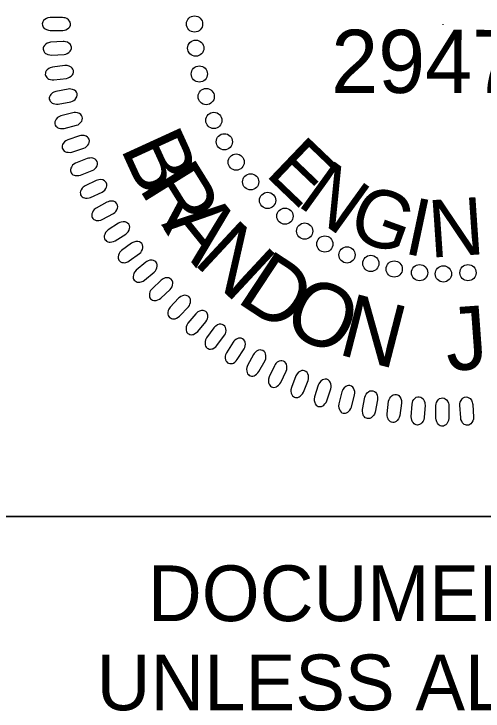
# Model space of a CAD drawing. Extents: x 505692 to 527456, y 415959 to 439886.
# Drawn here: x 507166.5 to 507212.8, y 439679.4 to 439748.2 of the extents above; entities that cross this region are included whole.
import ezdxf

# ---------------------------------------------------------------- set-up
doc = ezdxf.new("R2010")
doc.units = 0
for name, color, linetype in [('Sheet PE Seal Cell', 7, 'Continuous'), ('Sheet Profile CELL', 7, 'Continuous'), ('Sheet Sticker Exception Certification CELL', 7, 'Continuous')]:
    doc.layers.add(name, color=color, linetype=linetype)

msp = doc.modelspace()

# ---------------------------------------------------------------- linework, layer by layer
at = {"layer": 'Sheet PE Seal Cell'}
msp.add_line((507208.804, 439747.184), (507208.804, 439747.137), dxfattribs=at)
for points in [[(507171.257, 439747.846), (507170.03, 439747.847), (507169.811, 439747.809), (507169.671, 439747.758), (507169.501, 439747.645), (507169.391, 439747.548), (507169.312, 439747.435), (507169.272, 439747.331), (507169.252, 439747.219), (507169.272, 439747.107), (507169.302, 439746.987), (507169.361, 439746.883), (507169.461, 439746.778), (507169.541, 439746.718), (507169.691, 439746.651), (507169.87, 439746.591), (507170.029, 439746.569), (507171.287, 439746.561), (507171.455, 439746.583), (507171.596, 439746.628), (507171.755, 439746.718), (507171.894, 439746.83), (507171.975, 439746.927), (507172.034, 439747.084), (507172.054, 439747.233), (507172.014, 439747.383), (507171.964, 439747.487), (507171.865, 439747.615), (507171.695, 439747.734), (507171.516, 439747.801), (507171.386, 439747.831)], [(507171.309, 439745.489), (507170.085, 439745.412), (507169.868, 439745.361), (507169.732, 439745.301), (507169.569, 439745.178), (507169.466, 439745.074), (507169.393, 439744.957), (507169.36, 439744.85), (507169.348, 439744.737), (507169.375, 439744.627), (507169.412, 439744.509), (507169.478, 439744.408), (507169.584, 439744.31), (507169.667, 439744.255), (507169.821, 439744.198), (507170.004, 439744.149), (507170.164, 439744.136), (507171.419, 439744.208), (507171.587, 439744.241), (507171.723, 439744.294), (507171.877, 439744.394), (507172.009, 439744.514), (507172.083, 439744.616), (507172.133, 439744.776), (507172.143, 439744.927), (507172.094, 439745.074), (507172.038, 439745.175), (507171.931, 439745.296), (507171.754, 439745.404), (507171.57, 439745.46), (507171.439, 439745.482)], [(507171.474, 439743.108), (507170.257, 439742.955), (507170.044, 439742.89), (507169.911, 439742.821), (507169.757, 439742.688), (507169.66, 439742.578), (507169.595, 439742.457), (507169.569, 439742.348), (507169.563, 439742.234), (507169.597, 439742.126), (507169.642, 439742.011), (507169.714, 439741.914), (507169.827, 439741.823), (507169.913, 439741.773), (507170.069, 439741.725), (507170.255, 439741.688), (507170.416, 439741.686), (507171.664, 439741.836), (507171.829, 439741.879), (507171.962, 439741.941), (507172.11, 439742.05), (507172.234, 439742.178), (507172.301, 439742.285), (507172.341, 439742.448), (507172.342, 439742.599), (507172.284, 439742.743), (507172.221, 439742.84), (507172.106, 439742.954), (507171.923, 439743.051), (507171.736, 439743.095), (507171.604, 439743.109)], [(507171.807, 439740.782), (507170.602, 439740.553), (507170.393, 439740.475), (507170.266, 439740.398), (507170.12, 439740.255), (507170.031, 439740.14), (507169.974, 439740.015), (507169.954, 439739.905), (507169.955, 439739.791), (507169.996, 439739.684), (507170.048, 439739.573), (507170.126, 439739.481), (507170.244, 439739.397), (507170.333, 439739.353), (507170.493, 439739.314), (507170.68, 439739.289), (507170.841, 439739.297), (507172.077, 439739.525), (507172.239, 439739.579), (507172.368, 439739.649), (507172.508, 439739.767), (507172.624, 439739.903), (507172.684, 439740.014), (507172.714, 439740.179), (507172.705, 439740.33), (507172.638, 439740.469), (507172.57, 439740.563), (507172.448, 439740.668), (507172.259, 439740.754), (507172.07, 439740.787), (507171.937, 439740.791)], [(507172.287, 439738.441), (507171.098, 439738.137), (507170.895, 439738.046), (507170.773, 439737.961), (507170.636, 439737.81), (507170.554, 439737.688), (507170.505, 439737.56), (507170.492, 439737.449), (507170.501, 439737.335), (507170.548, 439737.232), (507170.607, 439737.123), (507170.69, 439737.037), (507170.813, 439736.96), (507170.906, 439736.921), (507171.067, 439736.894), (507171.256, 439736.881), (507171.416, 439736.898), (507172.635, 439737.203), (507172.794, 439737.267), (507172.917, 439737.345), (507173.05, 439737.472), (507173.157, 439737.615), (507173.21, 439737.728), (507173.23, 439737.896), (507173.212, 439738.046), (507173.136, 439738.18), (507173.061, 439738.269), (507172.934, 439738.368), (507172.74, 439738.441), (507172.549, 439738.463), (507172.416, 439738.459)], [(507172.941, 439736.157), (507171.774, 439735.778), (507171.577, 439735.675), (507171.46, 439735.583), (507171.333, 439735.423), (507171.259, 439735.297), (507171.218, 439735.166), (507171.212, 439735.054), (507171.228, 439734.941), (507171.281, 439734.841), (507171.347, 439734.736), (507171.436, 439734.655), (507171.563, 439734.587), (507171.657, 439734.554), (507171.82, 439734.536), (507172.01, 439734.535), (507172.168, 439734.563), (507173.366, 439734.944), (507173.52, 439735.018), (507173.639, 439735.103), (507173.763, 439735.238), (507173.861, 439735.387), (507173.907, 439735.505), (507173.915, 439735.672), (507173.888, 439735.821), (507173.804, 439735.951), (507173.725, 439736.035), (507173.591, 439736.125), (507173.393, 439736.186), (507173.201, 439736.195), (507173.068, 439736.183)], [(507173.699, 439733.92), (507172.558, 439733.469), (507172.368, 439733.353), (507172.257, 439733.254), (507172.141, 439733.087), (507172.075, 439732.956), (507172.042, 439732.822), (507172.043, 439732.711), (507172.066, 439732.599), (507172.125, 439732.503), (507172.197, 439732.402), (507172.291, 439732.327), (507172.423, 439732.266), (507172.519, 439732.24), (507172.683, 439732.232), (507172.872, 439732.243), (507173.028, 439732.28), (507174.2, 439732.735), (507174.349, 439732.819), (507174.462, 439732.912), (507174.578, 439733.054), (507174.666, 439733.21), (507174.705, 439733.329), (507174.703, 439733.497), (507174.666, 439733.644), (507174.574, 439733.768), (507174.489, 439733.847), (507174.35, 439733.929), (507174.148, 439733.977), (507173.956, 439733.974), (507173.825, 439733.953)], [(507174.599, 439731.761), (507173.488, 439731.239), (507173.306, 439731.111), (507173.202, 439731.005), (507173.096, 439730.831), (507173.038, 439730.696), (507173.014, 439730.561), (507173.022, 439730.449), (507173.052, 439730.339), (507173.118, 439730.247), (507173.196, 439730.151), (507173.294, 439730.082), (507173.429, 439730.03), (507173.527, 439730.009), (507173.691, 439730.012), (507173.879, 439730.035), (507174.032, 439730.082), (507175.173, 439730.61), (507175.317, 439730.703), (507175.424, 439730.802), (507175.53, 439730.951), (507175.61, 439731.112), (507175.64, 439731.234), (507175.627, 439731.402), (507175.582, 439731.546), (507175.482, 439731.664), (507175.392, 439731.737), (507175.248, 439731.81), (507175.044, 439731.845), (507174.852, 439731.831), (507174.723, 439731.802)], [(507175.646, 439729.612), (507174.571, 439729.021), (507174.397, 439728.883), (507174.299, 439728.77), (507174.205, 439728.59), (507174.155, 439728.452), (507174.14, 439728.315), (507174.155, 439728.204), (507174.192, 439728.096), (507174.263, 439728.008), (507174.347, 439727.918), (507174.449, 439727.855), (507174.588, 439727.811), (507174.686, 439727.797), (507174.85, 439727.81), (507175.036, 439727.844), (507175.187, 439727.901), (507176.292, 439728.499), (507176.429, 439728.601), (507176.53, 439728.708), (507176.626, 439728.863), (507176.695, 439729.028), (507176.718, 439729.152), (507176.695, 439729.318), (507176.64, 439729.459), (507176.533, 439729.571), (507176.439, 439729.639), (507176.291, 439729.702), (507176.085, 439729.725), (507175.894, 439729.698), (507175.767, 439729.661)], [(507176.803, 439727.537), (507175.766, 439726.88), (507175.601, 439726.731), (507175.511, 439726.613), (507175.428, 439726.427), (507175.387, 439726.286), (507175.38, 439726.148), (507175.403, 439726.039), (507175.446, 439725.933), (507175.523, 439725.85), (507175.612, 439725.765), (507175.719, 439725.708), (507175.859, 439725.673), (507175.958, 439725.666), (507176.121, 439725.689), (507176.304, 439725.735), (507176.451, 439725.801), (507177.516, 439726.467), (507177.647, 439726.577), (507177.741, 439726.691), (507177.828, 439726.851), (507177.886, 439727.021), (507177.901, 439727.146), (507177.867, 439727.31), (507177.804, 439727.447), (507177.691, 439727.552), (507177.593, 439727.613), (507177.44, 439727.668), (507177.233, 439727.678), (507177.045, 439727.638), (507176.92, 439727.594)], [(507178.079, 439725.563), (507177.086, 439724.841), (507176.931, 439724.682), (507176.848, 439724.558), (507176.777, 439724.368), (507176.745, 439724.225), (507176.747, 439724.087), (507176.776, 439723.979), (507176.826, 439723.876), (507176.907, 439723.797), (507177.002, 439723.718), (507177.112, 439723.668), (507177.254, 439723.643), (507177.354, 439723.641), (507177.515, 439723.674), (507177.695, 439723.731), (507177.837, 439723.807), (507178.858, 439724.539), (507178.982, 439724.657), (507179.069, 439724.776), (507179.145, 439724.942), (507179.192, 439725.114), (507179.2, 439725.24), (507179.157, 439725.402), (507179.084, 439725.535), (507178.964, 439725.632), (507178.862, 439725.688), (507178.707, 439725.733), (507178.5, 439725.729), (507178.315, 439725.678), (507178.193, 439725.627)], [(507179.483, 439723.681), (507178.537, 439722.899), (507178.392, 439722.731), (507178.317, 439722.602), (507178.258, 439722.407), (507178.235, 439722.262), (507178.245, 439722.125), (507178.281, 439722.019), (507178.338, 439721.92), (507178.424, 439721.846), (507178.524, 439721.773), (507178.636, 439721.73), (507178.78, 439721.714), (507178.879, 439721.718), (507179.038, 439721.762), (507179.214, 439721.83), (507179.351, 439721.914), (507180.325, 439722.709), (507180.441, 439722.834), (507180.52, 439722.958), (507180.586, 439723.129), (507180.622, 439723.304), (507180.622, 439723.43), (507180.568, 439723.589), (507180.488, 439723.717), (507180.362, 439723.806), (507180.257, 439723.855), (507180.099, 439723.89), (507179.892, 439723.875), (507179.71, 439723.812), (507179.592, 439723.752)], [(507180.993, 439721.91), (507180.098, 439721.071), (507179.964, 439720.894), (507179.897, 439720.76), (507179.85, 439720.562), (507179.837, 439720.416), (507179.856, 439720.28), (507179.898, 439720.176), (507179.96, 439720.081), (507180.052, 439720.013), (507180.156, 439719.946), (507180.27, 439719.911), (507180.415, 439719.903), (507180.514, 439719.914), (507180.67, 439719.967), (507180.841, 439720.046), (507180.973, 439720.139), (507181.894, 439720.993), (507182.003, 439721.126), (507182.073, 439721.254), (507182.129, 439721.428), (507182.154, 439721.606), (507182.145, 439721.731), (507182.082, 439721.887), (507181.993, 439722.009), (507181.862, 439722.091), (507181.754, 439722.133), (507181.594, 439722.158), (507181.389, 439722.129), (507181.212, 439722.055), (507181.097, 439721.988)], [(507182.728, 439720.132), (507181.888, 439719.238), (507181.765, 439719.053), (507181.707, 439718.915), (507181.673, 439718.715), (507181.668, 439718.567), (507181.696, 439718.433), (507181.745, 439718.333), (507181.813, 439718.241), (507181.908, 439718.179), (507182.016, 439718.119), (507182.133, 439718.091), (507182.278, 439718.092), (507182.375, 439718.109), (507182.528, 439718.172), (507182.694, 439718.262), (507182.82, 439718.362), (507183.685, 439719.274), (507183.785, 439719.412), (507183.848, 439719.545), (507183.892, 439719.723), (507183.906, 439719.901), (507183.889, 439720.026), (507183.817, 439720.177), (507183.72, 439720.294), (507183.584, 439720.367), (507183.474, 439720.402), (507183.313, 439720.417), (507183.11, 439720.375), (507182.938, 439720.29), (507182.827, 439720.216)], [(507184.418, 439718.602), (507183.635, 439717.657), (507183.525, 439717.464), (507183.475, 439717.323), (507183.454, 439717.121), (507183.459, 439716.974), (507183.494, 439716.841), (507183.549, 439716.744), (507183.623, 439716.657), (507183.722, 439716.602), (507183.833, 439716.548), (507183.952, 439716.527), (507184.097, 439716.538), (507184.194, 439716.56), (507184.341, 439716.633), (507184.501, 439716.733), (507184.62, 439716.842), (507185.427, 439717.805), (507185.518, 439717.95), (507185.572, 439718.087), (507185.605, 439718.266), (507185.608, 439718.445), (507185.584, 439718.569), (507185.501, 439718.715), (507185.398, 439718.826), (507185.258, 439718.89), (507185.145, 439718.918), (507184.984, 439718.923), (507184.784, 439718.868), (507184.617, 439718.773), (507184.512, 439718.692)], [(507186.199, 439717.202), (507185.478, 439716.209), (507185.379, 439716.01), (507185.339, 439715.866), (507185.33, 439715.663), (507185.344, 439715.516), (507185.388, 439715.386), (507185.449, 439715.293), (507185.528, 439715.21), (507185.63, 439715.161), (507185.745, 439715.115), (507185.865, 439715.101), (507186.008, 439715.121), (507186.103, 439715.15), (507186.245, 439715.232), (507186.399, 439715.342), (507186.511, 439715.457), (507187.256, 439716.469), (507187.338, 439716.619), (507187.383, 439716.759), (507187.405, 439716.94), (507187.397, 439717.12), (507187.365, 439717.241), (507187.273, 439717.382), (507187.164, 439717.486), (507187.019, 439717.542), (507186.905, 439717.562), (507186.744, 439717.557), (507186.548, 439717.49), (507186.387, 439717.384), (507186.287, 439717.297)], [(507188.101, 439715.788), (507187.443, 439714.752), (507187.357, 439714.547), (507187.326, 439714.401), (507187.329, 439714.198), (507187.353, 439714.054), (507187.405, 439713.926), (507187.471, 439713.836), (507187.556, 439713.76), (507187.661, 439713.716), (507187.778, 439713.677), (507187.899, 439713.672), (507188.04, 439713.7), (507188.134, 439713.735), (507188.271, 439713.825), (507188.417, 439713.944), (507188.522, 439714.067), (507189.202, 439715.124), (507189.273, 439715.279), (507189.31, 439715.421), (507189.32, 439715.604), (507189.301, 439715.782), (507189.261, 439715.901), (507189.161, 439716.036), (507189.045, 439716.133), (507188.898, 439716.179), (507188.783, 439716.193), (507188.622, 439716.178), (507188.431, 439716.099), (507188.277, 439715.983), (507188.182, 439715.89)], [(507190.118, 439714.573), (507189.527, 439713.498), (507189.454, 439713.288), (507189.432, 439713.14), (507189.449, 439712.938), (507189.481, 439712.794), (507189.541, 439712.67), (507189.613, 439712.585), (507189.703, 439712.513), (507189.81, 439712.477), (507189.929, 439712.446), (507190.05, 439712.447), (507190.19, 439712.485), (507190.28, 439712.525), (507190.412, 439712.624), (507190.551, 439712.753), (507190.647, 439712.882), (507191.259, 439713.979), (507191.321, 439714.138), (507191.349, 439714.283), (507191.348, 439714.465), (507191.317, 439714.642), (507191.27, 439714.759), (507191.161, 439714.887), (507191.04, 439714.976), (507190.89, 439715.013), (507190.774, 439715.02), (507190.615, 439714.994), (507190.428, 439714.903), (507190.282, 439714.778), (507190.194, 439714.679)], [(507192.178, 439713.466), (507191.656, 439712.357), (507191.596, 439712.142), (507191.583, 439711.994), (507191.613, 439711.792), (507191.654, 439711.651), (507191.721, 439711.532), (507191.799, 439711.451), (507191.892, 439711.385), (507192.002, 439711.356), (507192.123, 439711.332), (507192.243, 439711.341), (507192.38, 439711.387), (507192.469, 439711.433), (507192.593, 439711.54), (507192.724, 439711.677), (507192.812, 439711.812), (507193.354, 439712.945), (507193.406, 439713.109), (507193.424, 439713.254), (507193.412, 439713.436), (507193.37, 439713.611), (507193.316, 439713.724), (507193.199, 439713.845), (507193.072, 439713.927), (507192.92, 439713.955), (507192.804, 439713.954), (507192.647, 439713.918), (507192.467, 439713.816), (507192.329, 439713.681), (507192.247, 439713.577)], [(507194.306, 439712.458), (507193.854, 439711.318), (507193.807, 439711.1), (507193.804, 439710.951), (507193.846, 439710.751), (507193.896, 439710.614), (507193.971, 439710.499), (507194.053, 439710.423), (507194.151, 439710.363), (507194.262, 439710.34), (507194.385, 439710.324), (507194.504, 439710.34), (507194.638, 439710.396), (507194.723, 439710.447), (507194.84, 439710.562), (507194.962, 439710.706), (507195.042, 439710.846), (507195.512, 439712.012), (507195.553, 439712.178), (507195.562, 439712.324), (507195.538, 439712.505), (507195.486, 439712.676), (507195.424, 439712.787), (507195.301, 439712.9), (507195.169, 439712.974), (507195.015, 439712.991), (507194.9, 439712.983), (507194.745, 439712.938), (507194.571, 439712.824), (507194.442, 439712.682), (507194.367, 439712.573)], [(507196.514, 439711.556), (507196.135, 439710.389), (507196.102, 439710.169), (507196.109, 439710.02), (507196.163, 439709.824), (507196.221, 439709.69), (507196.304, 439709.579), (507196.39, 439709.509), (507196.491, 439709.455), (507196.604, 439709.44), (507196.727, 439709.431), (507196.845, 439709.455), (507196.975, 439709.519), (507197.057, 439709.576), (507197.167, 439709.697), (507197.279, 439709.849), (507197.35, 439709.994), (507197.746, 439711.186), (507197.777, 439711.355), (507197.777, 439711.502), (507197.741, 439711.681), (507197.678, 439711.848), (507197.61, 439711.954), (507197.48, 439712.06), (507197.344, 439712.125), (507197.189, 439712.133), (507197.074, 439712.118), (507196.922, 439712.063), (507196.757, 439711.939), (507196.637, 439711.788), (507196.569, 439711.674)], [(507198.847, 439710.883), (507198.541, 439709.695), (507198.523, 439709.474), (507198.539, 439709.325), (507198.605, 439709.132), (507198.672, 439709.002), (507198.761, 439708.897), (507198.852, 439708.832), (507198.956, 439708.785), (507199.069, 439708.777), (507199.193, 439708.776), (507199.309, 439708.807), (507199.435, 439708.878), (507199.513, 439708.94), (507199.615, 439709.069), (507199.718, 439709.228), (507199.779, 439709.377), (507200.1, 439710.592), (507200.12, 439710.761), (507200.111, 439710.908), (507200.064, 439711.085), (507199.99, 439711.248), (507199.916, 439711.349), (507199.779, 439711.447), (507199.639, 439711.503), (507199.484, 439711.502), (507199.37, 439711.479), (507199.222, 439711.415), (507199.065, 439711.28), (507198.954, 439711.122), (507198.894, 439711.005)], [(507202.369, 439710.095), (507202.139, 439708.89), (507202.061, 439708.682), (507201.983, 439708.554), (507201.841, 439708.409), (507201.725, 439708.32), (507201.6, 439708.262), (507201.49, 439708.242), (507201.376, 439708.244), (507201.27, 439708.285), (507201.158, 439708.337), (507201.066, 439708.415), (507200.982, 439708.532), (507200.938, 439708.622), (507200.9, 439708.782), (507200.875, 439708.969), (507200.883, 439709.13), (507201.112, 439710.366), (507201.166, 439710.528), (507201.236, 439710.657), (507201.354, 439710.797), (507201.49, 439710.913), (507201.601, 439710.973), (507201.766, 439711.002), (507201.917, 439710.993), (507202.056, 439710.926), (507202.15, 439710.858), (507202.256, 439710.737), (507202.341, 439710.547), (507202.374, 439710.358), (507202.378, 439710.226)], [(507204.735, 439709.769), (507204.581, 439708.552), (507204.516, 439708.339), (507204.447, 439708.207), (507204.314, 439708.053), (507204.204, 439707.956), (507204.083, 439707.891), (507203.974, 439707.865), (507203.86, 439707.859), (507203.752, 439707.893), (507203.637, 439707.938), (507203.54, 439708.01), (507203.45, 439708.123), (507203.4, 439708.209), (507203.352, 439708.366), (507203.315, 439708.551), (507203.313, 439708.713), (507203.463, 439709.96), (507203.507, 439710.125), (507203.57, 439710.259), (507203.678, 439710.405), (507203.807, 439710.53), (507203.913, 439710.597), (507204.076, 439710.637), (507204.227, 439710.637), (507204.371, 439710.579), (507204.468, 439710.516), (507204.582, 439710.402), (507204.678, 439710.219), (507204.723, 439710.032), (507204.737, 439709.899)], [(507207.053, 439709.572), (507206.975, 439708.347), (507206.924, 439708.131), (507206.863, 439707.995), (507206.74, 439707.832), (507206.637, 439707.728), (507206.52, 439707.657), (507206.413, 439707.623), (507206.299, 439707.611), (507206.189, 439707.638), (507206.071, 439707.675), (507205.971, 439707.741), (507205.873, 439707.848), (507205.817, 439707.931), (507205.76, 439708.084), (507205.711, 439708.267), (507205.699, 439708.428), (507205.771, 439709.683), (507205.804, 439709.85), (507205.858, 439709.987), (507205.958, 439710.14), (507206.078, 439710.273), (507206.18, 439710.346), (507206.341, 439710.396), (507206.491, 439710.406), (507206.638, 439710.357), (507206.739, 439710.301), (507206.86, 439710.193), (507206.968, 439710.016), (507207.024, 439709.832), (507207.045, 439709.702)], [(507211.773, 439709.622), (507211.849, 439708.398), (507211.826, 439708.177), (507211.783, 439708.034), (507211.681, 439707.857), (507211.591, 439707.742), (507211.484, 439707.656), (507211.382, 439707.609), (507211.271, 439707.582), (507211.159, 439707.596), (507211.037, 439707.618), (507210.929, 439707.671), (507210.818, 439707.764), (507210.753, 439707.84), (507210.677, 439707.985), (507210.606, 439708.16), (507210.574, 439708.318), (507210.488, 439709.572), (507210.499, 439709.743), (507210.536, 439709.885), (507210.616, 439710.049), (507210.718, 439710.196), (507210.811, 439710.281), (507210.963, 439710.351), (507211.112, 439710.38), (507211.263, 439710.35), (507211.371, 439710.307), (507211.504, 439710.215), (507211.634, 439710.053), (507211.712, 439709.878), (507211.75, 439709.751)], [(507209.406, 439709.5), (507209.405, 439708.273), (507209.368, 439708.054), (507209.315, 439707.914), (507209.203, 439707.744), (507209.106, 439707.635), (507208.993, 439707.555), (507208.89, 439707.515), (507208.777, 439707.496), (507208.665, 439707.515), (507208.545, 439707.545), (507208.44, 439707.605), (507208.336, 439707.705), (507208.276, 439707.785), (507208.209, 439707.935), (507208.149, 439708.114), (507208.127, 439708.274), (507208.12, 439709.53), (507208.142, 439709.699), (507208.188, 439709.839), (507208.277, 439709.999), (507208.389, 439710.138), (507208.487, 439710.218), (507208.644, 439710.278), (507208.793, 439710.298), (507208.943, 439710.258), (507209.047, 439710.208), (507209.175, 439710.109), (507209.293, 439709.939), (507209.361, 439709.759), (507209.39, 439709.629)]]:
    msp.add_lwpolyline(points, close=True, dxfattribs=at)
for centre in [(507184.296, 439747.211), (507184.414, 439744.82), (507184.772, 439742.271), (507185.448, 439740.04), (507186.204, 439737.689), (507187.238, 439735.577), (507188.407, 439733.573), (507189.84, 439731.621), (507191.511, 439729.788), (507193.223, 439728.234), (507195.173, 439726.759), (507197.163, 439725.484), (507199.353, 439724.407), (507201.702, 439723.57), (507204.011, 439723.012), (507206.519, 439722.652), (507211.296, 439722.651), (507208.868, 439722.532)]:
    msp.add_circle(centre, 0.801, dxfattribs=at)
at = {"layer": 'Sheet Profile CELL'}
msp.add_lwpolyline([(507158.628, 439811.094), (507258.678, 439811.094), (507258.678, 439698.594), (507158.628, 439698.594)], close=True, dxfattribs=at)
at = {"layer": 'Sheet Sticker Exception Certification CELL'}
msp.add_line((507158.628, 439698.594), (507358.665, 439698.594), dxfattribs=at)
msp.add_line((507158.628, 439698.594), (507358.665, 439698.594), dxfattribs=at)

# ---------------------------------------------------------------- texts
at = {"layer": 'Sheet PE Seal Cell'}
for s, height, rotation, p in [('29470', 6.2363, 359.98136, (507197.791, 439740.399)), ('B', 6.236, 294.5897, (507176.921, 439734.96)), ('E', 5.669, 316.26559, (507191.161, 439732.339)), ('R', 6.236, 301.86473, (507178.732, 439731.004)), ('N', 5.669, 324.20538, (507194.296, 439729.384)), ('G', 5.669, 340.08498, (507199.19, 439726.285)), ('I', 5.669, 348.02477, (507204.818, 439724.596)), ('N', 5.669, 3.90437, (507207.572, 439724.123)), ('A', 6.236, 308.98157, (507180.974, 439727.386)), ('N', 6.236, 317.09274, (507184.054, 439723.638)), ('D', 6.236, 326.58243, (507188.283, 439719.857)), ('O', 6.236, 335.45066, (507192.75, 439716.998)), ('N', 6.236, 345.5505, (507198.301, 439714.627)), ('J', 6.236, 4.1457, (507209.252, 439712.935))]:
    msp.add_text(s, height=height, rotation=rotation, dxfattribs=at).set_placement(p)
at = {"layer": 'Sheet Sticker Exception Certification CELL'}
for s, p in [('DOCUMENT NOT CONSIDERED FINAL', (507179.698, 439688.249)), ('DOCUMENT NOT CONSIDERED FINAL', (507179.698, 439688.249)), ('UNLESS ALL SIGNATURES COMPLETED', (507174.627, 439679.449)), ('UNLESS ALL SIGNATURES COMPLETED', (507174.627, 439679.449))]:
    msp.add_text(s, height=5.5, dxfattribs=at).set_placement(p)

doc.saveas('drawing.dxf')
